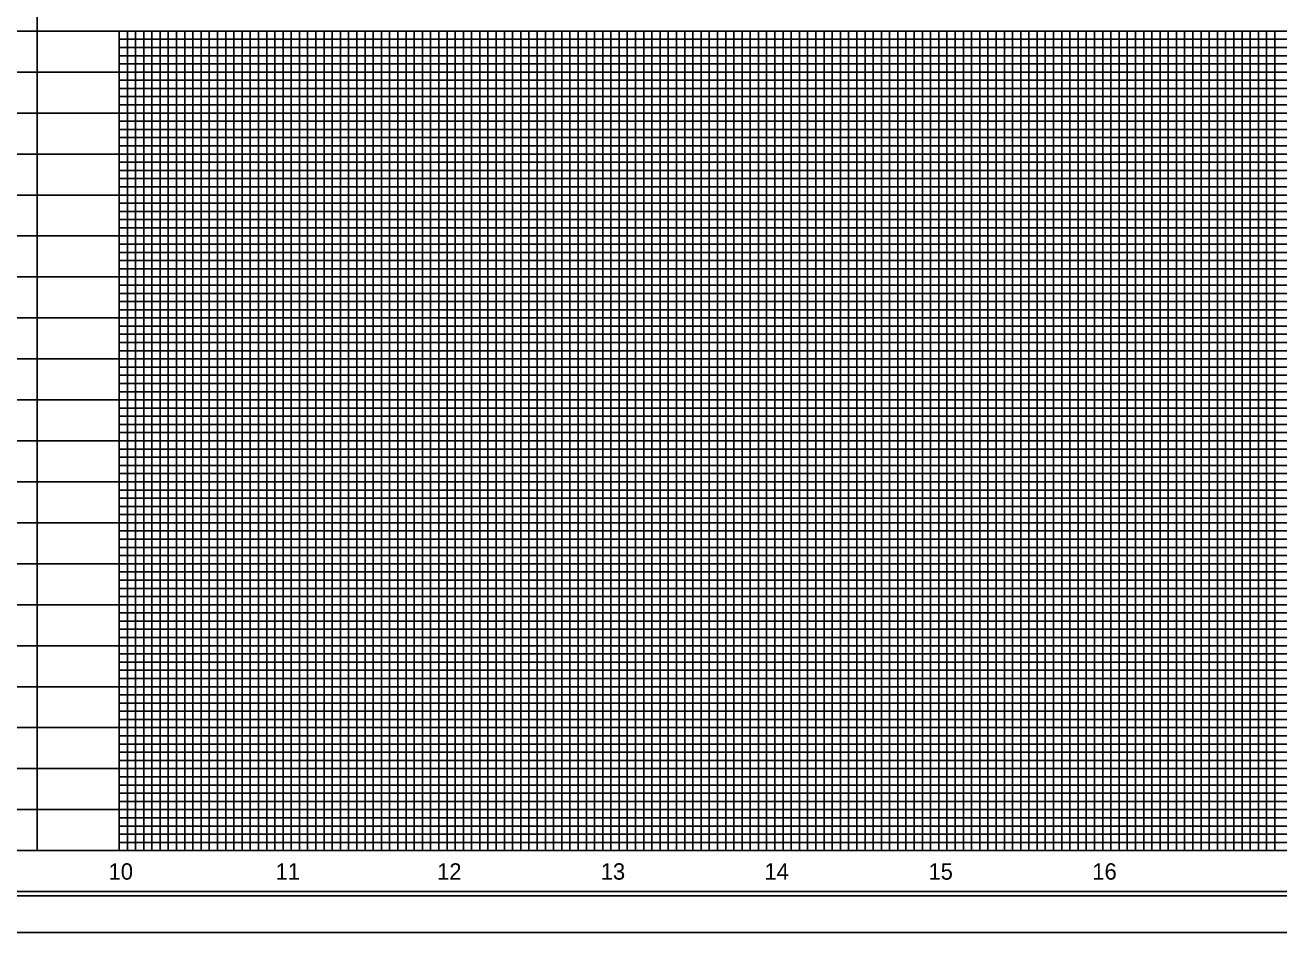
# Model space of a CAD drawing. Extents: x 1967929 to 1975641, y 546296 to 568534.
# Drawn here: x 1970574 to 1971339, y 566323 to 566888 of the extents above; entities that cross this region are included whole.
import ezdxf

# ---------------------------------------------------------------- set-up
doc = ezdxf.new("R2010")
doc.units = 0
for name, color, linetype in [('Exist Vertical Profile Horizontal Axis Label Major', 7, 'Continuous'), ('Scratch_Level_3', 7, 'Continuous'), ('Sheet Cutting Line CELL', 7, 'Continuous'), ('Sheet Plot Border Inside CELL', 7, 'Continuous'), ('Sheet Plot Border Outside CELL', 7, 'Continuous'), ('Sheet Profile CELL', 7, 'Continuous'), ('Sheet Profile Grid Major CELL', 7, 'Continuous'), ('Sheet Profile Grid Middle CELL', 7, 'Continuous'), ('Sheet Profile Grid Minor CELL', 7, 'Continuous')]:
    doc.layers.add(name, color=color, linetype=linetype)

msp = doc.modelspace()

# ---------------------------------------------------------------- linework, layer by layer
at = {"layer": 'Scratch_Level_3'}
for points in [[(1970081.45, 566983.86), (1970081.45, 566483.86), (1970581.45, 566483.86), (1970581.45, 566683.86), (1970581.45, 566803.86), (1970581.45, 566983.86)], [(1970081.45, 566883.86), (1970081.45, 566383.86), (1971481.45, 566383.86), (1971481.45, 566883.86)], [(1970081.45, 566883.86), (1970081.45, 566383.86), (1971381.45, 566383.86), (1971381.45, 566883.86)], [(1970081.45, 566883.86), (1970081.45, 566383.86), (1971481.45, 566383.86), (1971481.45, 566883.86)], [(1970581.45, 566883.86), (1970581.45, 566383.86), (1971481.45, 566383.86), (1971481.45, 566578.86), (1971481.45, 566703.86), (1971481.45, 566883.86)]]:
    msp.add_lwpolyline(points, close=True, dxfattribs=at)
at = {"layer": 'Sheet Cutting Line CELL'}
msp.add_line((1969864.45, 566333.86), (1971548.45, 566333.86), dxfattribs=at)
at = {"layer": 'Sheet Plot Border Inside CELL'}
msp.add_lwpolyline([(1969877.45, 566356.31), (1971543.95, 566356.31), (1971543.95, 567411.41), (1969877.45, 567411.41)], close=True, dxfattribs=at)
at = {"layer": 'Sheet Plot Border Outside CELL'}
for points in [[(1969864.45, 566333.86), (1971548.45, 566333.86), (1971548.45, 567433.86), (1969864.45, 567433.86)], [(1969864.45, 565233.86), (1971548.45, 565233.86), (1971548.45, 566333.86), (1969864.45, 566333.86)]]:
    msp.add_lwpolyline(points, close=True, dxfattribs=at)
at = {"layer": 'Sheet Profile CELL'}
for p, q in [((1971531.45, 566883.86), (1970031.45, 566883.86)), ((1971531.45, 566383.86), (1970031.45, 566383.86))]:
    msp.add_line(p, q, dxfattribs=at)
msp.add_lwpolyline([(1971531.45, 567408.86), (1970031.45, 567408.86), (1970031.45, 566358.86), (1971531.45, 566358.86)], close=True, dxfattribs=at)
at = {"layer": 'Sheet Profile Grid Major CELL'}
for points in [[(1971531.45, 566833.86), (1970031.45, 566833.86), (1970031.45, 566883.86), (1971531.45, 566883.86)], [(1970581.45, 566883.86), (1970581.45, 566383.86), (1970631.45, 566383.86), (1970631.45, 566883.86)], [(1970681.45, 566883.86), (1970681.45, 566383.86), (1970731.45, 566383.86), (1970731.45, 566883.86)], [(1970781.45, 566883.86), (1970781.45, 566383.86), (1970831.45, 566383.86), (1970831.45, 566883.86)], [(1970881.45, 566883.86), (1970881.45, 566383.86), (1970931.45, 566383.86), (1970931.45, 566883.86)], [(1970981.45, 566883.86), (1970981.45, 566383.86), (1971031.45, 566383.86), (1971031.45, 566883.86)], [(1971081.45, 566883.86), (1971081.45, 566383.86), (1971131.45, 566383.86), (1971131.45, 566883.86)], [(1971181.45, 566883.86), (1971181.45, 566383.86), (1971231.45, 566383.86), (1971231.45, 566883.86)], [(1971281.45, 566883.86), (1971281.45, 566383.86), (1971331.45, 566383.86), (1971331.45, 566883.86)], [(1971531.45, 566733.86), (1970031.45, 566733.86), (1970031.45, 566783.86), (1971531.45, 566783.86)], [(1971531.45, 566633.86), (1970031.45, 566633.86), (1970031.45, 566683.86), (1971531.45, 566683.86)], [(1971531.45, 566533.86), (1970031.45, 566533.86), (1970031.45, 566583.86), (1971531.45, 566583.86)], [(1971531.45, 566433.86), (1970031.45, 566433.86), (1970031.45, 566483.86), (1971531.45, 566483.86)]]:
    msp.add_lwpolyline(points, dxfattribs=at)
at = {"layer": 'Sheet Profile Grid Middle CELL'}
for points in [[(1970031.45, 566883.86), (1970031.45, 566858.86), (1971531.45, 566858.86)], [(1970656.45, 566883.86), (1970656.45, 566383.86), (1970706.45, 566383.86), (1970706.45, 566883.86)], [(1970756.45, 566883.86), (1970756.45, 566383.86), (1970806.45, 566383.86), (1970806.45, 566883.86)], [(1970856.45, 566883.86), (1970856.45, 566383.86), (1970906.45, 566383.86), (1970906.45, 566883.86)], [(1970956.45, 566883.86), (1970956.45, 566383.86), (1971006.45, 566383.86), (1971006.45, 566883.86)], [(1971056.45, 566883.86), (1971056.45, 566383.86), (1971106.45, 566383.86), (1971106.45, 566883.86)], [(1971156.45, 566883.86), (1971156.45, 566383.86), (1971206.45, 566383.86), (1971206.45, 566883.86)], [(1971256.45, 566883.86), (1971256.45, 566383.86), (1971306.45, 566383.86), (1971306.45, 566883.86)], [(1971531.45, 566808.86), (1970031.45, 566808.86), (1970031.45, 566758.86), (1971531.45, 566758.86)], [(1971531.45, 566708.86), (1970031.45, 566708.86), (1970031.45, 566658.86), (1971531.45, 566658.86)], [(1971531.45, 566608.86), (1970031.45, 566608.86), (1970031.45, 566558.86), (1971531.45, 566558.86)], [(1971531.45, 566508.86), (1970031.45, 566508.86), (1970031.45, 566458.86), (1971531.45, 566458.86)], [(1971531.45, 566408.86), (1970031.45, 566408.86)]]:
    msp.add_lwpolyline(points, dxfattribs=at)
at = {"layer": 'Sheet Profile Grid Minor CELL'}
msp.add_line((1970636.45, 566383.86), (1970636.45, 566883.86), dxfattribs=at)
for points in [[(1970641.45, 566883.86), (1970641.45, 566383.86), (1970641.45, 566383.86), (1970646.45, 566383.86), (1970646.45, 566883.86)], [(1970651.45, 566883.86), (1970651.45, 566383.86), (1970661.45, 566383.86), (1970661.45, 566883.86)], [(1970666.45, 566883.86), (1970666.45, 566383.86), (1970671.45, 566383.86), (1970671.45, 566883.86)], [(1970676.45, 566883.86), (1970676.45, 566383.86), (1970686.45, 566383.86), (1970686.45, 566883.86)], [(1970691.45, 566883.86), (1970691.45, 566383.86), (1970696.45, 566383.86), (1970696.45, 566883.86)], [(1970701.45, 566883.86), (1970701.45, 566383.86), (1970711.45, 566383.86), (1970711.45, 566883.86)], [(1970716.45, 566883.86), (1970716.45, 566383.86), (1970721.45, 566383.86), (1970721.45, 566883.86)], [(1970726.45, 566883.86), (1970726.45, 566383.86), (1970736.45, 566383.86), (1970736.45, 566883.86)], [(1970741.45, 566883.86), (1970741.45, 566383.86), (1970746.45, 566383.86), (1970746.45, 566883.86)], [(1970751.45, 566883.86), (1970751.45, 566383.86), (1970761.45, 566383.86), (1970761.45, 566883.86)], [(1970766.45, 566883.86), (1970766.45, 566383.86), (1970771.45, 566383.86), (1970771.45, 566883.86)], [(1970776.45, 566883.86), (1970776.45, 566383.86), (1970786.45, 566383.86), (1970786.45, 566883.86)], [(1970791.45, 566883.86), (1970791.45, 566383.86)], [(1970791.45, 566383.86), (1970796.45, 566383.86), (1970796.45, 566883.86)], [(1970801.45, 566883.86), (1970801.45, 566383.86), (1970811.45, 566383.86), (1970811.45, 566883.86)], [(1970816.45, 566883.86), (1970816.45, 566383.86), (1970821.45, 566383.86), (1970821.45, 566883.86)], [(1970826.45, 566883.86), (1970826.45, 566383.86), (1970836.45, 566383.86), (1970836.45, 566883.86)], [(1970841.45, 566883.86), (1970841.45, 566383.86), (1970846.45, 566383.86), (1970846.45, 566883.86)], [(1970851.45, 566883.86), (1970851.45, 566383.86), (1970861.45, 566383.86), (1970861.45, 566883.86)], [(1970866.45, 566883.86), (1970866.45, 566383.86), (1970871.45, 566383.86), (1970871.45, 566883.86)], [(1970876.45, 566883.86), (1970876.45, 566383.86), (1970886.45, 566383.86), (1970886.45, 566883.86)], [(1970891.45, 566883.86), (1970891.45, 566383.86), (1970896.45, 566383.86), (1970896.45, 566883.86)], [(1970901.45, 566883.86), (1970901.45, 566383.86), (1970911.45, 566383.86), (1970911.45, 566883.86)], [(1970916.45, 566883.86), (1970916.45, 566383.86), (1970921.45, 566383.86), (1970921.45, 566883.86)], [(1970926.45, 566883.86), (1970926.45, 566383.86), (1970936.45, 566383.86), (1970936.45, 566883.86)], [(1970941.45, 566883.86), (1970941.45, 566383.86), (1970946.45, 566383.86), (1970946.45, 566883.86)], [(1970951.45, 566883.86), (1970951.45, 566383.86), (1970961.45, 566383.86), (1970961.45, 566883.86)], [(1970966.45, 566883.86), (1970966.45, 566383.86), (1970971.45, 566383.86), (1970971.45, 566883.86)], [(1970976.45, 566883.86), (1970976.45, 566383.86), (1970986.45, 566383.86), (1970986.45, 566883.86)], [(1970991.45, 566883.86), (1970991.45, 566383.86), (1970996.45, 566383.86), (1970996.45, 566883.86)], [(1971001.45, 566883.86), (1971001.45, 566383.86), (1971011.45, 566383.86), (1971011.45, 566883.86)], [(1971016.45, 566883.86), (1971016.45, 566383.86), (1971021.45, 566383.86), (1971021.45, 566883.86)], [(1971026.45, 566883.86), (1971026.45, 566383.86), (1971036.45, 566383.86), (1971036.45, 566883.86)], [(1971041.45, 566883.86), (1971041.45, 566383.86), (1971046.45, 566383.86), (1971046.45, 566883.86)], [(1971051.45, 566883.86), (1971051.45, 566383.86), (1971061.45, 566383.86), (1971061.45, 566883.86)], [(1971066.45, 566883.86), (1971066.45, 566383.86), (1971071.45, 566383.86), (1971071.45, 566883.86)], [(1971076.45, 566883.86), (1971076.45, 566383.86), (1971086.45, 566383.86), (1971086.45, 566883.86)], [(1971091.45, 566883.86), (1971091.45, 566383.86), (1971096.45, 566383.86), (1971096.45, 566883.86)], [(1971101.45, 566883.86), (1971101.45, 566383.86)], [(1971101.45, 566383.86), (1971111.45, 566383.86), (1971111.45, 566883.86)], [(1971116.45, 566883.86), (1971116.45, 566383.86), (1971121.45, 566383.86), (1971121.45, 566883.86)], [(1971126.45, 566883.86), (1971126.45, 566383.86), (1971136.45, 566383.86), (1971136.45, 566883.86)], [(1971141.45, 566883.86), (1971141.45, 566383.86), (1971146.45, 566383.86), (1971146.45, 566883.86)], [(1971151.45, 566883.86), (1971151.45, 566383.86), (1971161.45, 566383.86), (1971161.45, 566883.86)], [(1971166.45, 566883.86), (1971166.45, 566383.86), (1971171.45, 566383.86), (1971171.45, 566883.86)], [(1971176.45, 566883.86), (1971176.45, 566383.86), (1971186.45, 566383.86), (1971186.45, 566883.86)], [(1971191.45, 566883.86), (1971191.45, 566383.86), (1971196.45, 566383.86), (1971196.45, 566883.86)], [(1971201.45, 566883.86), (1971201.45, 566383.86), (1971211.45, 566383.86), (1971211.45, 566883.86)], [(1971216.45, 566883.86), (1971216.45, 566383.86), (1971221.45, 566383.86), (1971221.45, 566883.86)], [(1971226.45, 566883.86), (1971226.45, 566383.86), (1971236.45, 566383.86), (1971236.45, 566883.86)], [(1971241.45, 566883.86), (1971241.45, 566383.86), (1971246.45, 566383.86), (1971246.45, 566883.86)], [(1971251.45, 566883.86), (1971251.45, 566383.86), (1971261.45, 566383.86), (1971261.45, 566883.86)], [(1971266.45, 566883.86), (1971266.45, 566383.86), (1971271.45, 566383.86), (1971271.45, 566883.86)], [(1971276.45, 566883.86), (1971276.45, 566383.86), (1971286.45, 566383.86), (1971286.45, 566883.86)], [(1971291.45, 566883.86), (1971291.45, 566383.86), (1971296.45, 566383.86), (1971296.45, 566883.86)], [(1971301.45, 566883.86), (1971301.45, 566383.86), (1971311.45, 566383.86), (1971311.45, 566883.86)], [(1971316.45, 566883.86), (1971316.45, 566383.86), (1971321.45, 566383.86), (1971321.45, 566883.86)], [(1971326.45, 566883.86), (1971326.45, 566383.86), (1971336.45, 566383.86), (1971336.45, 566883.86)], [(1970631.45, 566878.86), (1971481.45, 566878.86)], [(1971481.45, 566873.86), (1970631.45, 566873.86)], [(1970631.45, 566868.86), (1971481.45, 566868.86)], [(1971481.45, 566863.86), (1970631.45, 566863.86)], [(1970631.45, 566853.86), (1971481.45, 566853.86)], [(1971481.45, 566848.86), (1970631.45, 566848.86)], [(1970631.45, 566843.86), (1971481.45, 566843.86)], [(1971481.45, 566838.86), (1970631.45, 566838.86)], [(1970631.45, 566828.86), (1971481.45, 566828.86)], [(1971481.45, 566823.86), (1970631.45, 566823.86)], [(1970631.45, 566818.86), (1971481.45, 566818.86)], [(1971481.45, 566813.86), (1970631.45, 566813.86)], [(1970631.45, 566803.86), (1971481.45, 566803.86)], [(1971481.45, 566798.86), (1970631.45, 566798.86)], [(1970631.45, 566793.86), (1971481.45, 566793.86)], [(1971481.45, 566788.86), (1970631.45, 566788.86)], [(1970631.45, 566778.86), (1971481.45, 566778.86)], [(1971481.45, 566773.86), (1970631.45, 566773.86)], [(1970631.45, 566768.86), (1971481.45, 566768.86)], [(1971481.45, 566763.86), (1970631.45, 566763.86)], [(1970631.45, 566753.86), (1971481.45, 566753.86)], [(1971481.45, 566748.86), (1970631.45, 566748.86)], [(1970631.45, 566743.86), (1971481.45, 566743.86)], [(1971481.45, 566738.86), (1970631.45, 566738.86)], [(1970631.45, 566728.86), (1971481.45, 566728.86)], [(1971481.45, 566723.86), (1970631.45, 566723.86)], [(1970631.45, 566718.86), (1971481.45, 566718.86)], [(1971481.45, 566713.86), (1970631.45, 566713.86)], [(1970631.45, 566703.86), (1971481.45, 566703.86)], [(1971481.45, 566698.86), (1970631.45, 566698.86)], [(1970631.45, 566693.86), (1971481.45, 566693.86)], [(1971481.45, 566688.86), (1970631.45, 566688.86)], [(1970631.45, 566678.86), (1971481.45, 566678.86)], [(1971481.45, 566673.86), (1970631.45, 566673.86)], [(1970631.45, 566668.86), (1971481.45, 566668.86)], [(1971481.45, 566663.86), (1970631.45, 566663.86)], [(1970631.45, 566653.86), (1971481.45, 566653.86)], [(1971481.45, 566648.86), (1970631.45, 566648.86)], [(1970631.45, 566643.86), (1971481.45, 566643.86)], [(1971481.45, 566638.86), (1970631.45, 566638.86)], [(1970631.45, 566628.86), (1971481.45, 566628.86)], [(1971481.45, 566623.86), (1970631.45, 566623.86)], [(1970631.45, 566618.86), (1971481.45, 566618.86)], [(1971481.45, 566613.86), (1970631.45, 566613.86)], [(1970631.45, 566603.86), (1971481.45, 566603.86)], [(1971481.45, 566598.86), (1970631.45, 566598.86)], [(1970631.45, 566593.86), (1971481.45, 566593.86)], [(1971481.45, 566588.86), (1970631.45, 566588.86)], [(1970631.45, 566578.86), (1971481.45, 566578.86)], [(1971481.45, 566573.86), (1970631.45, 566573.86)], [(1970631.45, 566568.86), (1971481.45, 566568.86)], [(1971481.45, 566563.86), (1970631.45, 566563.86)], [(1970631.45, 566553.86), (1971481.45, 566553.86)], [(1971481.45, 566548.86), (1970631.45, 566548.86)], [(1970631.45, 566543.86), (1971481.45, 566543.86)], [(1971481.45, 566538.86), (1970631.45, 566538.86)], [(1970631.45, 566528.86), (1971481.45, 566528.86)], [(1971481.45, 566523.86), (1970631.45, 566523.86)], [(1970631.45, 566518.86), (1971481.45, 566518.86)], [(1971481.45, 566513.86), (1970631.45, 566513.86)], [(1970631.45, 566503.86), (1971481.45, 566503.86)], [(1971481.45, 566498.86), (1970631.45, 566498.86)], [(1970631.45, 566493.86), (1971481.45, 566493.86)], [(1971481.45, 566488.86), (1970631.45, 566488.86)], [(1970631.45, 566478.86), (1971481.45, 566478.86)], [(1971481.45, 566473.86), (1970631.45, 566473.86)], [(1970631.45, 566468.86), (1971481.45, 566468.86)], [(1971481.45, 566463.86), (1970631.45, 566463.86)], [(1970631.45, 566453.86), (1971481.45, 566453.86)], [(1971481.45, 566448.86), (1970631.45, 566448.86)], [(1970631.45, 566443.86), (1971481.45, 566443.86)], [(1971481.45, 566438.86), (1970631.45, 566438.86)], [(1970631.45, 566428.86), (1971481.45, 566428.86)], [(1971481.45, 566423.86), (1970631.45, 566423.86)], [(1970631.45, 566418.86), (1971481.45, 566418.86)], [(1971481.45, 566413.86), (1970631.45, 566413.86)], [(1970631.45, 566403.86), (1971481.45, 566403.86)], [(1971481.45, 566398.86), (1970631.45, 566398.86)], [(1970631.45, 566393.86), (1971481.45, 566393.86)], [(1970531.45, 566388.86), (1970081.45, 566388.86), (1970081.45, 566383.86), (1971481.45, 566383.86)], [(1971481.45, 566388.86), (1970631.45, 566388.86)]]:
    msp.add_lwpolyline(points, dxfattribs=at)

# ---------------------------------------------------------------- texts
at = {"layer": 'Exist Vertical Profile Horizontal Axis Label Major'}
for s, p in [('10', (1970625.03, 566366.11)), ('11', (1970726.87, 566366.11)), ('12', (1970825.42, 566366.11)), ('13', (1970925.26, 566366.11)), ('14', (1971025.1, 566366.11)), ('15', (1971125.19, 566366.11)), ('16', (1971225.13, 566366.11))]:
    msp.add_text(s, height=10, dxfattribs=at).set_placement(p)

doc.saveas('drawing.dxf')
